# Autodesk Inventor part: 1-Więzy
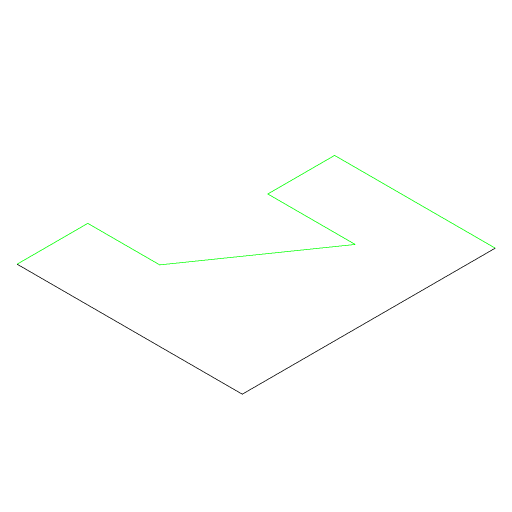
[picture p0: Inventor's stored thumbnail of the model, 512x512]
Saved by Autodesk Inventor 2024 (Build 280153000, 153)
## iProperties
Company: ATC
Shininess: 20.0
Length Units: 11269
Angle Units: 11279
Time Units: 11290
Mass Units: 11283
Length Display Precision: 1
Angle Display Precision: 1
Compacted: True
Created: 2023-03
Part Number: 1-Więzy
Document SubType Name: Modeling
Designer: Andrzej Jaskulski
Material: Kurs-AJ
Density: 1 g/cm^3
Appearance: Kurs-AJ
Checked By: A.J.
Engr Approved By: Andrzej Jaskulski
Mfg Approved By: Andrzej Jaskulski
Authority: A.J.
Density: 0.0
Volumn: 0.0
Area: 0.0
PropertySet Name: Model Information
Control State: 0
Master: False
Checked Out: False
Title: A.J.: Kurs R2024-MEP
Author: Andrzej Jaskulski
Revision Number: 1/24
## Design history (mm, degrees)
sketch "Ceownik"
  geometry: L1 (-11.929, 9.563)-(74.262, 9.563); L2 (74.262, 9.563)-(74.262, 106.374); L3 (74.262, 106.374)-(12.783, 106.374); L4 (12.783, 106.374)-(12.783, 80.808); L5 (12.783, 80.808)-(46.237, 80.808); L6 (46.237, 80.808)-(15.598, 36.621); L7 (15.598, 36.621)-(-11.929, 36.621); L8 (-11.929, 36.621)-(-11.929, 9.563)
  constraints: 16 end point, 4 horizontal, 3 vertical, 2 other
node "Korpusy bryłowe"
node "Korpusy powierzchniowe"
